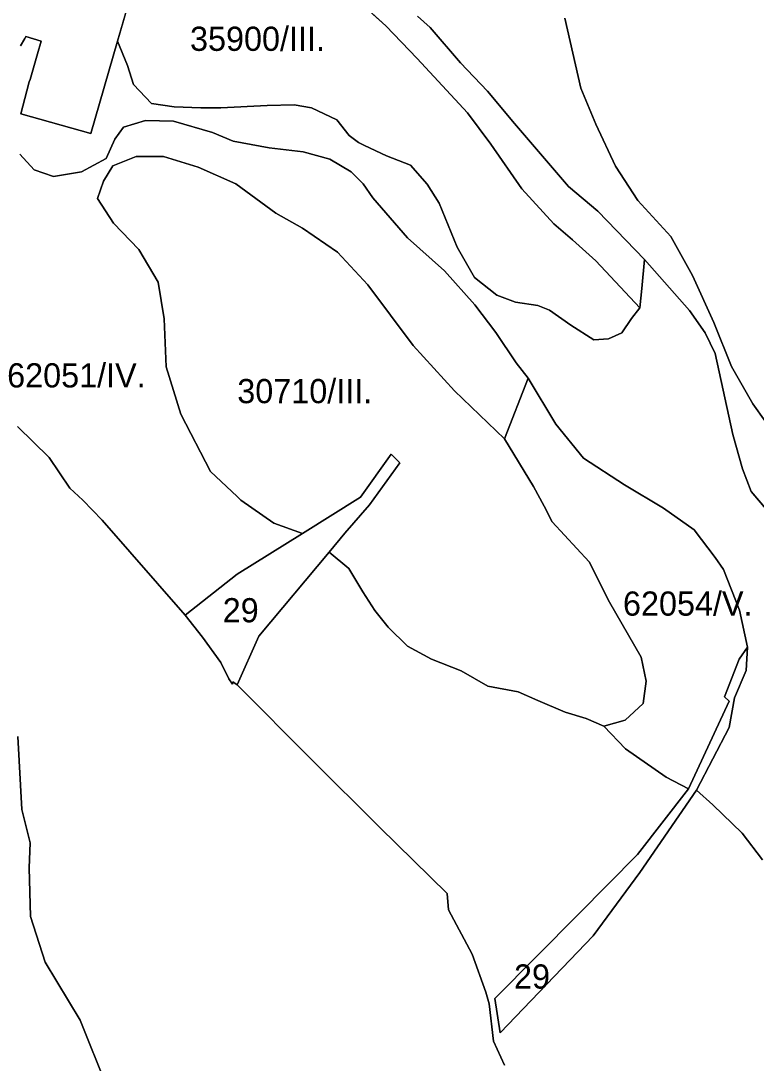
# Model space of a CAD drawing. Extents: x -521621 to -516761, y -1190184 to -1184927.
# Drawn here: x -518666 to -518211, y -1188092 to -1187446 of the extents above; entities that cross this region are included whole.
import ezdxf

# ---------------------------------------------------------------- set-up
doc = ezdxf.new("R2010")
doc.units = 0
doc.layers.add('BPEJ_s', color=7, linetype='Continuous')

msp = doc.modelspace()

# ---------------------------------------------------------------- linework, layer by layer
at = {"layer": 'BPEJ_s'}
for p, q in [((-518593.3, -1187413.32), (-518606.43, -1187458.65)), ((-518440.06, -1187448.96), (-518460.08, -1187430.81)), ((-518420.46, -1187443.14), (-518412.59, -1187450.15)), ((-518420.79, -1187469.37), (-518440.06, -1187448.96)), ((-518412.59, -1187450.15), (-518393.77, -1187472.04)), ((-518666.67, -1187461.38), (-518663.99, -1187456.89)), ((-518663.99, -1187456.89), (-518666.67, -1187461.38)), ((-518663.99, -1187456.89), (-518663.36, -1187455.62)), ((-518663.36, -1187455.62), (-518663.99, -1187456.89)), ((-518663.36, -1187455.62), (-518653.71, -1187458.46)), ((-518653.71, -1187458.46), (-518663.36, -1187455.62)), ((-518653.71, -1187458.46), (-518655.94, -1187466.45)), ((-518655.94, -1187466.45), (-518653.71, -1187458.46)), ((-518623, -1187515.83), (-518606.43, -1187458.65)), ((-518606.43, -1187458.65), (-518623, -1187515.83)), ((-518606.43, -1187458.65), (-518600.28, -1187473.59)), ((-518655.94, -1187466.45), (-518660.5, -1187482.32)), ((-518660.5, -1187482.32), (-518655.94, -1187466.45)), ((-518600.28, -1187473.59), (-518596.54, -1187485.39)), ((-518389.44, -1187503.02), (-518420.79, -1187469.37)), ((-518393.77, -1187472.04), (-518377.14, -1187489.56)), ((-518661.25, -1187483.84), (-518662.71, -1187489.43)), ((-518662.71, -1187489.43), (-518661.25, -1187483.84)), ((-518660.5, -1187482.32), (-518661.25, -1187483.84)), ((-518661.25, -1187483.84), (-518660.5, -1187482.32)), ((-518596.54, -1187485.39), (-518585.33, -1187497.19)), ((-518662.71, -1187489.43), (-518666.3, -1187503.51)), ((-518666.3, -1187503.51), (-518662.71, -1187489.43)), ((-518377.14, -1187489.56), (-518360.31, -1187509.5)), ((-518585.33, -1187497.19), (-518571.24, -1187499.21)), ((-518571.24, -1187499.21), (-518554.84, -1187499.78)), ((-518542.48, -1187499.78), (-518513.72, -1187498.34)), ((-518513.72, -1187498.34), (-518497.04, -1187498.05)), ((-518497.04, -1187498.05), (-518486.11, -1187499.78)), ((-518666.3, -1187503.51), (-518623, -1187515.83)), ((-518623, -1187515.83), (-518666.3, -1187503.51)), ((-518554.84, -1187499.78), (-518542.48, -1187499.78)), ((-518486.11, -1187499.78), (-518470.58, -1187507.26)), ((-518375.08, -1187522.38), (-518389.44, -1187503.02)), ((-518602.67, -1187511.89), (-518608.05, -1187519.34)), ((-518589.02, -1187507.76), (-518602.67, -1187511.89)), ((-518571.65, -1187508.17), (-518589.02, -1187507.76)), ((-518547.66, -1187515.21), (-518571.65, -1187508.17)), ((-518470.58, -1187507.26), (-518462.82, -1187517.05)), ((-518360.31, -1187509.5), (-518326.98, -1187548.56)), ((-518534.84, -1187520.58), (-518547.66, -1187515.21)), ((-518462.82, -1187517.05), (-518457.06, -1187521.36)), ((-518608.05, -1187519.34), (-518613.42, -1187531.34)), ((-518512.5, -1187524.72), (-518534.84, -1187520.58)), ((-518491.41, -1187527.21), (-518512.5, -1187524.72)), ((-518457.06, -1187521.36), (-518453.33, -1187523.33)), ((-518453.33, -1187523.33), (-518439.7, -1187529.54)), ((-518355.88, -1187550.04), (-518375.08, -1187522.38)), ((-518658.09, -1187538.38), (-518667.05, -1187528.51)), ((-518613.42, -1187531.34), (-518628.73, -1187539.62)), ((-518474.87, -1187531.76), (-518491.41, -1187527.21)), ((-518461.63, -1187539.62), (-518474.87, -1187531.76)), ((-518439.7, -1187529.54), (-518424.82, -1187535.43)), ((-518424.82, -1187535.43), (-518414.6, -1187547.21)), ((-518646.1, -1187542.52), (-518658.09, -1187538.38)), ((-518628.73, -1187539.62), (-518646.1, -1187542.52)), ((-518454.19, -1187547.07), (-518461.63, -1187539.62)), ((-518448.16, -1187555.63), (-518454.19, -1187547.07)), ((-518414.6, -1187547.21), (-518407.16, -1187558.99)), ((-518336.09, -1187571.71), (-518355.88, -1187550.04)), ((-518326.98, -1187548.56), (-518308.67, -1187563.99)), ((-518426.7, -1187580.55), (-518448.16, -1187555.63)), ((-518407.16, -1187558.99), (-518396.01, -1187586.27)), ((-518308.67, -1187563.99), (-518279.79, -1187593.89)), ((-518324.43, -1187581.73), (-518336.09, -1187571.71)), ((-518403.71, -1187600.87), (-518426.7, -1187580.55)), ((-518309.99, -1187594.71), (-518324.43, -1187581.73)), ((-518396.01, -1187586.27), (-518385.17, -1187605.18)), ((-518282.77, -1187623.84), (-518309.99, -1187594.71)), ((-518281.37, -1187612), (-518279.79, -1187593.89)), ((-518279.79, -1187593.89), (-518281.37, -1187612)), ((-518279.79, -1187593.89), (-518251.95, -1187625.46)), ((-518384.94, -1187621.96), (-518403.71, -1187600.87)), ((-518385.17, -1187605.18), (-518371.22, -1187616.03)), ((-518282.77, -1187623.84), (-518281.37, -1187612)), ((-518281.37, -1187612), (-518282.77, -1187623.84)), ((-518371.91, -1187639.21), (-518384.94, -1187621.96)), ((-518371.22, -1187616.03), (-518359.76, -1187620.37)), ((-518359.76, -1187620.37), (-518345.82, -1187622.54)), ((-518345.82, -1187622.54), (-518338.69, -1187625.33)), ((-518338.69, -1187625.33), (-518325.37, -1187634.64)), ((-518287.88, -1187630.6), (-518282.77, -1187623.84)), ((-518251.95, -1187625.46), (-518242.28, -1187639.37)), ((-518325.37, -1187634.64), (-518311.11, -1187643.63)), ((-518293.76, -1187639.29), (-518287.88, -1187630.6)), ((-518359.27, -1187658), (-518371.91, -1187639.21)), ((-518302.13, -1187643.01), (-518293.76, -1187639.29)), ((-518242.28, -1187639.37), (-518236.03, -1187652.27)), ((-518311.11, -1187643.63), (-518302.13, -1187643.01)), ((-518236.03, -1187652.27), (-518224.99, -1187702.39)), ((-518351.99, -1187667.58), (-518359.27, -1187658)), ((-518334.75, -1187695.96), (-518351.99, -1187667.58)), ((-518317.5, -1187717.04), (-518334.75, -1187695.96)), ((-518224.99, -1187702.39), (-518218.97, -1187723.71)), ((-518292.21, -1187733.53), (-518317.5, -1187717.04)), ((-518218.97, -1187723.71), (-518213.64, -1187737.85)), ((-518268.08, -1187748.1), (-518292.21, -1187733.53)), ((-518213.64, -1187737.85), (-518179.13, -1187778.41)), ((-518248.92, -1187761.52), (-518268.08, -1187748.1)), ((-518235.89, -1187778.77), (-518248.92, -1187761.52)), ((-518230.91, -1187786.05), (-518235.89, -1187778.77)), ((-518220.95, -1187811.36), (-518230.91, -1187786.05)), ((-518216.02, -1187834.34), (-518220.95, -1187811.36)), ((-518216.73, -1187848.74), (-518216.02, -1187834.34)), ((-518223.93, -1187865.78), (-518216.73, -1187848.74)), ((-518227.29, -1187884.03), (-518223.93, -1187865.78)), ((-518247.52, -1187922.9), (-518227.29, -1187884.03)), ((-518237.5, -1187932.03), (-518247.52, -1187922.9)), ((-518219.21, -1187949.69), (-518237.5, -1187932.03)), ((-518206.66, -1187966.08), (-518219.21, -1187949.69))]:
    msp.add_line(p, q, dxfattribs=at)
for points in [[(-518460.08, -1187430.81), (-518440.06, -1187448.96), (-518420.79, -1187469.37), (-518389.44, -1187503.02), (-518375.08, -1187522.38), (-518355.88, -1187550.04), (-518336.09, -1187571.71), (-518324.43, -1187581.73), (-518309.99, -1187594.71), (-518282.77, -1187623.84), (-518287.88, -1187630.6), (-518293.76, -1187639.29), (-518302.13, -1187643.01), (-518311.11, -1187643.63), (-518325.37, -1187634.64), (-518338.69, -1187625.33), (-518345.82, -1187622.54), (-518359.76, -1187620.37), (-518371.22, -1187616.03), (-518385.17, -1187605.18), (-518396.01, -1187586.27), (-518407.16, -1187558.99), (-518414.6, -1187547.21), (-518424.82, -1187535.43), (-518439.7, -1187529.54), (-518453.33, -1187523.33), (-518457.06, -1187521.36), (-518462.82, -1187517.05), (-518470.58, -1187507.26), (-518486.11, -1187499.78), (-518497.04, -1187498.05), (-518513.72, -1187498.34), (-518542.48, -1187499.78), (-518554.84, -1187499.78), (-518571.24, -1187499.21), (-518585.33, -1187497.19), (-518596.54, -1187485.39), (-518600.28, -1187473.59), (-518606.43, -1187458.65), (-518593.3, -1187413.32)], [(-518179.13, -1187778.41), (-518213.64, -1187737.85), (-518218.97, -1187723.71), (-518224.99, -1187702.39), (-518236.03, -1187652.27), (-518242.28, -1187639.37), (-518251.95, -1187625.46), (-518279.79, -1187593.89), (-518308.67, -1187563.99), (-518326.98, -1187548.56), (-518360.31, -1187509.5), (-518377.14, -1187489.56), (-518393.77, -1187472.04), (-518412.59, -1187450.15), (-518420.46, -1187443.14)], [(-518182.04, -1187726.48), (-518212.64, -1187683.44), (-518225.88, -1187660.26), (-518236.75, -1187633.08), (-518250.08, -1187603.94), (-518263.4, -1187579.76), (-518283.85, -1187557.44), (-518297.79, -1187536.05), (-518309.87, -1187510), (-518319.17, -1187487.68), (-518329.08, -1187444.28)], [(-518329.08, -1187444.28), (-518319.17, -1187487.68), (-518309.87, -1187510), (-518297.79, -1187536.05), (-518283.85, -1187557.44), (-518263.4, -1187579.76), (-518250.08, -1187603.94), (-518236.75, -1187633.08), (-518225.88, -1187660.26), (-518212.64, -1187683.44), (-518182.04, -1187726.48)], [(-518667.05, -1187528.51), (-518658.09, -1187538.38), (-518646.1, -1187542.52), (-518628.73, -1187539.62), (-518613.42, -1187531.34), (-518608.05, -1187519.34), (-518602.67, -1187511.89), (-518589.02, -1187507.76), (-518571.65, -1187508.17), (-518547.66, -1187515.21), (-518534.84, -1187520.58), (-518512.5, -1187524.72), (-518491.41, -1187527.21), (-518474.87, -1187531.76), (-518461.63, -1187539.62), (-518454.19, -1187547.07), (-518448.16, -1187555.63), (-518426.7, -1187580.55), (-518403.71, -1187600.87), (-518384.94, -1187621.96), (-518371.91, -1187639.21), (-518359.27, -1187658), (-518351.99, -1187667.58), (-518366.55, -1187705.16), (-518397.58, -1187675.25), (-518423.26, -1187647.26), (-518451.23, -1187609.69), (-518470, -1187589.37), (-518491.84, -1187574.42), (-518508.37, -1187565.28), (-518533.18, -1187547.07), (-518556.35, -1187536.73), (-518577.85, -1187530.1), (-518594.81, -1187530.1), (-518609.29, -1187535.9), (-518615.08, -1187545.42), (-518618.8, -1187556.18), (-518608.87, -1187571.49), (-518593.16, -1187587.63), (-518581.16, -1187607.91), (-518577.44, -1187630.67), (-518576.2, -1187660.47), (-518567.1, -1187689.85), (-518548.9, -1187725.44), (-518532.24, -1187740.76), (-518530.04, -1187743.14), (-518509.52, -1187757.45), (-518491.77, -1187763.79), (-518532.32, -1187789.11), (-518564.51, -1187814.54), (-518616, -1187755.54), (-518627.98, -1187743.09), (-518635.92, -1187735.63), (-518648.89, -1187716.63), (-518668.36, -1187697.39)], [(-518668.36, -1187697.39), (-518648.89, -1187716.63), (-518635.92, -1187735.63), (-518627.98, -1187743.09), (-518616, -1187755.54), (-518564.51, -1187814.54), (-518553.67, -1187828.1), (-518542.49, -1187843.69), (-518537.41, -1187853.86), (-518535.18, -1187857.25), (-518534.87, -1187855.67), (-518532.35, -1187857.56), (-518486.1, -1187903.85), (-518443.93, -1187946.05), (-518402.09, -1187986.99), (-518401.33, -1187997.12), (-518386.62, -1188024.55), (-518378.15, -1188048.15), (-518376.14, -1188055.41), (-518373.32, -1188078.61), (-518366.54, -1188093.37)], [(-518366.54, -1188093.37), (-518373.32, -1188078.61), (-518376.14, -1188055.41), (-518378.15, -1188048.15), (-518386.62, -1188024.55), (-518401.33, -1187997.12), (-518402.09, -1187986.99), (-518443.93, -1187946.05), (-518486.1, -1187903.85), (-518532.35, -1187857.56), (-518518.77, -1187827.42), (-518475.28, -1187775.29), (-518463.15, -1187785.5), (-518454.36, -1187799.99), (-518447.03, -1187811.54), (-518438.78, -1187821.81), (-518426.7, -1187833.59), (-518411.76, -1187841.65), (-518393.37, -1187848.93), (-518376.89, -1187858.52), (-518358.12, -1187861.97), (-518345.86, -1187867.33), (-518329, -1187874.62), (-518315.97, -1187878.45), (-518304.93, -1187883.29), (-518291.53, -1187897.33), (-518266.43, -1187914.79), (-518252.55, -1187922.03), (-518284.22, -1187962.9), (-518320.72, -1187999.74), (-518372.51, -1188052.19), (-518369.28, -1188073.36), (-518311.65, -1188013.26), (-518282.69, -1187974.05), (-518247.52, -1187922.9), (-518237.5, -1187932.03), (-518219.21, -1187949.69), (-518206.66, -1187966.08)], [(-518612.92, -1188107.21), (-518629.6, -1188065.48), (-518651.29, -1188029.6), (-518660.46, -1188001.22), (-518661.29, -1187971.18), (-518660.49, -1187955.69), (-518665.7, -1187934.84), (-518668.3, -1187889.66)], [(-518668.3, -1187889.66), (-518665.7, -1187934.84), (-518660.49, -1187955.69), (-518661.29, -1187971.18), (-518660.46, -1188001.22), (-518651.29, -1188029.6), (-518629.6, -1188065.48), (-518612.92, -1188107.21)]]:
    msp.add_lwpolyline(points, dxfattribs=at)
for points in [[(-518491.77, -1187763.79), (-518509.52, -1187757.45), (-518530.04, -1187743.14), (-518532.24, -1187740.76), (-518548.9, -1187725.44), (-518567.1, -1187689.85), (-518576.2, -1187660.47), (-518577.44, -1187630.67), (-518581.16, -1187607.91), (-518593.16, -1187587.63), (-518608.87, -1187571.49), (-518618.8, -1187556.18), (-518615.08, -1187545.42), (-518609.29, -1187535.9), (-518594.81, -1187530.1), (-518577.85, -1187530.1), (-518556.35, -1187536.73), (-518533.18, -1187547.07), (-518508.37, -1187565.28), (-518491.84, -1187574.42), (-518470, -1187589.37), (-518451.23, -1187609.69), (-518423.26, -1187647.26), (-518397.58, -1187675.25), (-518366.55, -1187705.16), (-518348.54, -1187734.68), (-518342.03, -1187746.95), (-518337.04, -1187756.53), (-518314.06, -1187781.45), (-518301.41, -1187806.37), (-518281.87, -1187840.5), (-518278.8, -1187855.45), (-518280.72, -1187869.25), (-518291.83, -1187879.6), (-518304.93, -1187883.29), (-518315.97, -1187878.45), (-518329, -1187874.62), (-518345.86, -1187867.33), (-518358.12, -1187861.97), (-518376.89, -1187858.52), (-518393.37, -1187848.93), (-518411.76, -1187841.65), (-518426.7, -1187833.59), (-518438.78, -1187821.81), (-518447.03, -1187811.54), (-518454.36, -1187799.99), (-518463.15, -1187785.5), (-518475.28, -1187775.29), (-518465.59, -1187763.68), (-518450.34, -1187746.05), (-518431.37, -1187719.94), (-518436.79, -1187714.52), (-518455.76, -1187741.3)], [(-518366.55, -1187705.16), (-518351.99, -1187667.58), (-518334.75, -1187695.96), (-518317.5, -1187717.04), (-518292.21, -1187733.53), (-518268.08, -1187748.1), (-518248.92, -1187761.52), (-518235.89, -1187778.77), (-518230.91, -1187786.05), (-518220.95, -1187811.36), (-518216.02, -1187834.34), (-518221.05, -1187841.78), (-518230.17, -1187865.06), (-518227.29, -1187867.7), (-518252.55, -1187922.03), (-518266.43, -1187914.79), (-518291.53, -1187897.33), (-518304.93, -1187883.29), (-518291.83, -1187879.6), (-518280.72, -1187869.25), (-518278.8, -1187855.45), (-518281.87, -1187840.5), (-518301.41, -1187806.37), (-518314.06, -1187781.45), (-518337.04, -1187756.53), (-518342.03, -1187746.95), (-518348.54, -1187734.68)], [(-518564.51, -1187814.54), (-518532.32, -1187789.11), (-518491.77, -1187763.79), (-518455.76, -1187741.3), (-518436.79, -1187714.52), (-518431.37, -1187719.94), (-518450.34, -1187746.05), (-518465.59, -1187763.68), (-518475.28, -1187775.29), (-518518.77, -1187827.42), (-518532.35, -1187857.56), (-518534.87, -1187855.67), (-518535.18, -1187857.25), (-518537.41, -1187853.86), (-518542.49, -1187843.69), (-518553.67, -1187828.1)], [(-518252.55, -1187922.03), (-518227.29, -1187867.7), (-518230.17, -1187865.06), (-518221.05, -1187841.78), (-518216.02, -1187834.34), (-518216.73, -1187848.74), (-518223.93, -1187865.78), (-518227.29, -1187884.03), (-518247.52, -1187922.9), (-518282.69, -1187974.05), (-518311.65, -1188013.26), (-518369.28, -1188073.36), (-518372.51, -1188052.19), (-518320.72, -1187999.74), (-518284.22, -1187962.9)]]:
    msp.add_lwpolyline(points, close=True, dxfattribs=at)

# ---------------------------------------------------------------- texts
for s, p in [('35900/III.', (-518561.5, -1187464.56)), ('62051/IV.', (-518674.85, -1187673.25)), ('30710/III.', (-518532.22, -1187683.01)), ('62054/V.', (-518293.13, -1187814.75)), ('29', (-518541.23, -1187818.88)), ('29', (-518360.69, -1188045.97))]:
    msp.add_text(s, height=15, dxfattribs=at).set_placement(p)

doc.saveas('drawing.dxf')
